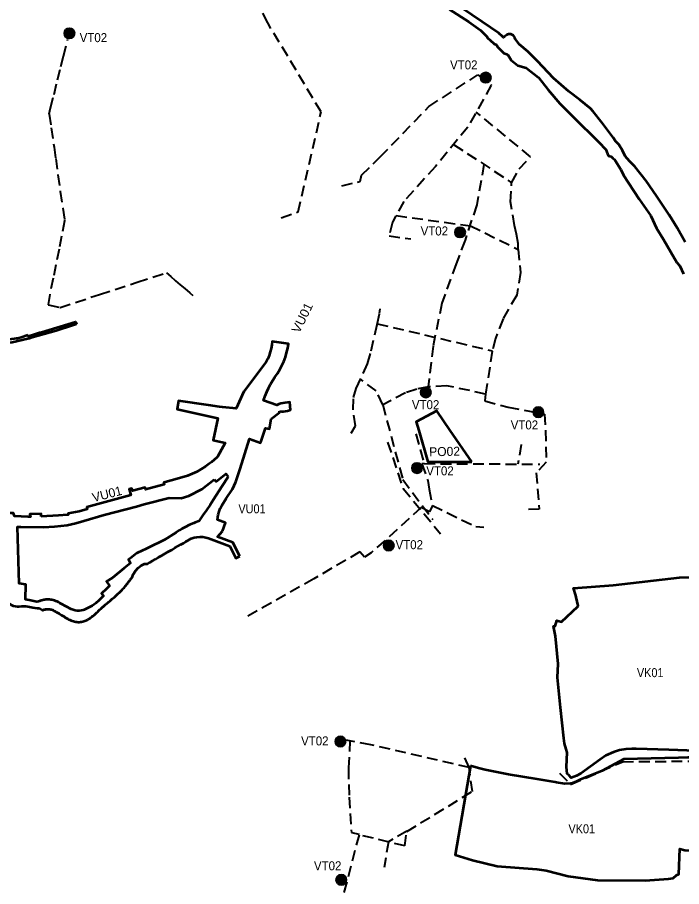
# Model space of a CAD drawing. Extents: x -650145 to -642675, y -1074338 to -1066803.
# Drawn here: x -646647 to -645175, y -1071056 to -1069131 of the extents above; entities that cross this region are included whole.
import ezdxf

# ---------------------------------------------------------------- set-up
doc = ezdxf.new("R2010")
doc.units = 0
doc.header["$LTSCALE"] = 8
doc.linetypes.add('MEDIUM_DASHED', pattern=[4.5, 3, -1.5])
for name, color, linetype, lineweight in [('12', 7, 'MEDIUM_DASHED', 40), ('13', 7, 'MEDIUM_DASHED', 40), ('15', 7, 'Continuous', 13), ('44', 7, 'Continuous', 53), ('45', 7, 'Continuous', 53), ('46', 7, 'Continuous', 53), ('53', 7, 'Continuous', 53)]:
    doc.layers.add(name, color=color, linetype=linetype, lineweight=lineweight)
for name, color, linetype in [('17', 7, 'Continuous'), ('2', 7, 'Continuous'), ('5', 7, 'Continuous'), ('8', 7, 'Continuous')]:
    doc.layers.add(name, color=color, linetype=linetype)

msp = doc.modelspace()

# ---------------------------------------------------------------- hatches: boundary and pattern name
at = {"layer": '15'}
for points in [[(-646519.621, -1069166.048, 1), (-646543.146, -1069166.048, 1)], [(-645597.068, -1069264.181, 1), (-645620.593, -1069264.181, 1)], [(-645654.023, -1069606.85, 1), (-645677.548, -1069606.85, 1)], [(-645729.982, -1069961.372, 1), (-645753.507, -1069961.372, 1)], [(-645480.488, -1070005.174, 1), (-645504.013, -1070005.174, 1)], [(-645749.33, -1070128.96, 1), (-645772.855, -1070128.96, 1)], [(-645812.096, -1070300.527, 1), (-645835.621, -1070300.527, 1)], [(-645919.09, -1070734.667, 1), (-645942.615, -1070734.667, 1)], [(-645917.104, -1071041.111, 1), (-645940.629, -1071041.111, 1)]]:
    msp.add_hatch(color=256, dxfattribs=at).paths.add_polyline_path(points)

# ---------------------------------------------------------------- linework, layer by layer
at = {"layer": '12'}
for p, q in [((-645679.959, -1069412.046), (-645551.493, -1069496.874)), ((-645849.328, -1069809.196), (-645594.304, -1069869.281)), ((-645530.465, -1070076.92), (-645537.502, -1070120.198)), ((-645787.95, -1070966.128), (-645887.342, -1070941.864))]:
    msp.add_line(p, q, dxfattribs=at)
for points in [[(-646062.183, -1069574.695), (-646024.736, -1069561.612), (-645973.562, -1069340.254), (-646092.013, -1069143.037), (-646157.557, -1069015.41), (-646220.085, -1068916.892), (-646248.016, -1068862.258), (-646295.932, -1068894.5), (-646451.322, -1069032.874)], [(-646576.25, -1069344.69), (-646576.07, -1069344.19), (-646572.92, -1069331.38), (-646565.43, -1069301.45), (-646557.53, -1069269.39), (-646550.09, -1069239.83), (-646544.34, -1069216.84), (-646534.934, -1069179.318)], [(-645927.806, -1069503.664), (-645886.806, -1069494.297), (-645883.788, -1069480.205), (-645842.55, -1069439.942), (-645734.927, -1069328.215), (-645626.154, -1069257.704), (-645596.435, -1069280.712), (-645648.533, -1069373.739), (-645720.378, -1069461.316), (-645790.62, -1069538.59), (-645815.779, -1069584.682), (-645822.696, -1069614.711), (-645775.097, -1069621.255)], [(-646576.25, -1069344.69), (-646576.14, -1069345.28), (-646571.6, -1069375.24), (-646565.13, -1069418.25), (-646561.67, -1069443.36), (-646557.02, -1069479.48), (-646551.76, -1069516.65), (-646546.19, -1069553.66), (-646542.189, -1069579.489), (-646541.86, -1069581.61), (-646548.99, -1069615.32), (-646554.11, -1069644.37), (-646561.65, -1069679.08), (-646567.03, -1069708.57), (-646575.01, -1069744.61), (-646578.22, -1069766.52), (-646578.238, -1069766.625), (-646578.433, -1069767.754), (-646552.777, -1069773.113), (-646552.12, -1069773.25), (-646464.51, -1069744.51), (-646380.87, -1069717.23), (-646346.59, -1069706.12), (-646316.394, -1069696.504), (-646316.32, -1069696.48), (-646306.32, -1069704.97), (-646296.979, -1069713.37), (-646296.125, -1069714.146), (-646285.929, -1069723.39), (-646275.84, -1069731.47), (-646264.46, -1069741.23), (-646257.888, -1069746.914)], [(-645807.67, -1069569.827), (-645642.853, -1069592.369), (-645537.006, -1069644.608), (-645537.068, -1069631.54), (-645540.509, -1069610.611), (-645545.036, -1069592.007), (-645553.718, -1069539.481), (-645551.493, -1069496.874), (-645535.107, -1069466.529), (-645509.579, -1069439.682), (-645629.872, -1069340.417)], [(-645612.686, -1069456.467), (-645628.75, -1069545.873), (-645654.668, -1069623.875), (-645674.387, -1069676.46), (-645706.032, -1069763.934), (-645725.616, -1069858.975), (-645736.083, -1069949.319)], [(-645537.006, -1069644.608), (-645531.552, -1069695.67), (-645540.071, -1069746.311), (-645570.504, -1069798.227), (-645587.257, -1069841.96), (-645594.542, -1069870.205), (-645609.199, -1069964.997), (-645695.3, -1069946.789), (-645735.674, -1069949.294), (-645761.611, -1069954.176), (-645786.679, -1069962.538), (-645837.185, -1069988.794), (-645851.6, -1069958.035), (-645886.355, -1069931.852)], [(-645906.816, -1070051.7), (-645897.34, -1070035.615), (-645902.834, -1069999.35), (-645901.735, -1069972.609), (-645895.874, -1069952.462), (-645870.943, -1069898.484), (-645862.678, -1069869.213), (-645849.656, -1069810.695), (-645844.459, -1069786.925), (-645843.101, -1069776.602)], [(-645609.199, -1069964.997), (-645611.007, -1069980.138), (-645559.306, -1069994.087), (-645478.278, -1070009.272), (-645476.409, -1070045.777), (-645475.095, -1070115.938), (-645496.905, -1070139.324), (-645490.337, -1070219.995), (-645518.762, -1070220.564)], [(-645837.185, -1069988.794), (-645792.73, -1070154.35), (-645726.373, -1070242.826)], [(-645763.769, -1070053.49), (-645745.016, -1070119.16), (-645488.654, -1070120.442)], [(-645826.322, -1070071.476), (-645791.882, -1070174.421), (-645708.828, -1070274.697)], [(-645745.016, -1070119.16), (-645750.773, -1070119.546), (-645737.216, -1070156.772), (-645734.164, -1070175.48), (-645727.06, -1070211.99), (-645630.95, -1070258.73), (-645613.049, -1070260.16)], [(-645727.06, -1070211.99), (-645733.17, -1070225.623), (-645751.944, -1070216.719), (-645862.549, -1070316.813), (-645877.139, -1070326.682), (-645887.867, -1070314.667), (-645989.89, -1070374.31), (-646136.792, -1070457.926)], [(-645645.314, -1070792.546), (-645863.469, -1070742.026), (-645925.077, -1070730.137)], [(-645909.628, -1070733.118), (-645913.153, -1070793.741), (-645911.597, -1070858.189), (-645906.549, -1070936.386), (-645889.059, -1070939.608)], [(-645638.383, -1070845.262), (-645645.314, -1070792.546), (-645658.84, -1070762.42)], [(-645787.95, -1070966.128), (-645783.846, -1070933.893), (-645638.383, -1070845.262)], [(-645783.721, -1070932.909), (-645824.424, -1070957.108), (-645833.925, -1071014.113)], [(-645889.511, -1070941.335), (-645965.547, -1071232.088), (-646030.617, -1071380.071), (-646083.181, -1071471.838), (-646148.926, -1071551.731), (-646210.712, -1071621.148), (-646257.454, -1071581.884), (-646334.001, -1071528.434)]]:
    msp.add_lwpolyline(points, dxfattribs=at)
at = {"layer": '13'}
msp.add_lwpolyline([(-645445.374, -1070804.496), (-645420.722, -1070830.204), (-645305.382, -1070779.425), (-645079.923, -1070777.683), (-644892.766, -1070773.328), (-644498.43, -1070726.295), (-644498.43, -1070726.295), (-644443.224, -1070697.577)], dxfattribs=at)
at = {"layer": '15', "lineweight": 35}
for centre in [(-646531.383, -1069166.048), (-645608.83, -1069264.181), (-645665.785, -1069606.85), (-645741.744, -1069961.372), (-645492.25, -1070005.174), (-645761.092, -1070128.96), (-645823.858, -1070300.527), (-645930.852, -1070734.667), (-645928.866, -1071041.111)]:
    msp.add_circle(centre, 11.762, dxfattribs=at)
at = {"layer": '44'}
for points in [[(-646515.63, -1069810.24), (-646522.32, -1069812.28), (-646560.92, -1069825.33), (-646613.65, -1069840.02), (-646620.06, -1069841.69), (-646629.83, -1069844.23), (-646635.93, -1069845.82), (-646658.5, -1069850.59), (-646689.73, -1069854.58), (-646705.87, -1069856.62), (-646717.66, -1069857.11), (-646729.54, -1069853.69)], [(-646593.34, -1069827.68), (-646518.19, -1069805.27), (-646515.63, -1069810.24)], [(-646729.24, -1069851.41), (-646723.5, -1069852.83), (-646719.82, -1069853.78), (-646689.63, -1069849.7), (-646689.8, -1069848.71), (-646664.22, -1069843.72), (-646648.18, -1069841.04), (-646648.28, -1069841.78), (-646638.34, -1069838.73), (-646623.31, -1069834.1)], [(-646623.31, -1069834.1), (-646622.54, -1069835.88), (-646622.19, -1069836.71), (-646597.29, -1069828.86), (-646593.34, -1069827.68)]]:
    msp.add_lwpolyline(points, dxfattribs=at)
at = {"layer": '45'}
for points in [[(-645688.87, -1069113.44), (-645646.08, -1069140.37), (-645620.2, -1069159.26), (-645606.11, -1069172.98), (-645603.91, -1069176.86), (-645599, -1069181.48), (-645590.41, -1069189.45), (-645584.73, -1069191.88), (-645582.63, -1069195.88), (-645568.9, -1069209.87), (-645562.17, -1069212.02), (-645560.72, -1069214.25), (-645559.33, -1069214.54), (-645552.2, -1069225.59), (-645537.44, -1069237.41), (-645519.59, -1069242.38), (-645491.63, -1069264.25), (-645470.44, -1069291.24), (-645444.62, -1069321.35), (-645405.7, -1069360.27), (-645368.13, -1069397.37), (-645358.04, -1069406.84), (-645342.49, -1069423.06), (-645339.31, -1069433.27), (-645336.66, -1069437.47), (-645330.57, -1069438.89), (-645327.2, -1069442.53), (-645323.36, -1069445.79), (-645322.13, -1069447.96), (-645309.62, -1069467.79), (-645303.57, -1069480.49), (-645268.57, -1069533.23), (-645242.75, -1069570.26), (-645230.42, -1069597.39), (-645230.42, -1069597.39)], [(-645253.4, -1069493.06), (-645278.31, -1069461.33), (-645290.5, -1069449.03), (-645299.61, -1069437.97), (-645306.16, -1069425.55), (-645314.14, -1069412.54), (-645321.1, -1069405.21), (-645326.59, -1069396.64), (-645350.63, -1069363.98), (-645371.12, -1069339.47), (-645376.38, -1069332.65), (-645400.07, -1069313.32), (-645424.8, -1069295.24), (-645458.45, -1069265.56), (-645494.13, -1069227.63), (-645515.89, -1069206.66), (-645534.25, -1069190.56), (-645543.43, -1069178.39), (-645544.154, -1069175.682), (-645544.448, -1069174.993), (-645545.631, -1069172.966), (-645547.269, -1069171.107), (-645548.594, -1069170.034), (-645550.076, -1069169.141), (-645551.674, -1069168.459), (-645553.344, -1069168.007), (-645555.036, -1069167.793), (-645556.702, -1069167.808), (-645558.298, -1069168.035), (-645559.793, -1069168.445), (-645561.162, -1069169.007), (-645561.794, -1069169.334), (-645562.95, -1069170.06), (-645567.5, -1069173.46), (-645569.81, -1069175.03), (-645571.9, -1069173.43), (-645579.94, -1069165.52), (-645616.63, -1069140.8), (-645662.44, -1069109.89)], [(-645166.67, -1069629), (-645184.88, -1069596.58), (-645202.56, -1069568.23), (-645230.1, -1069525.98), (-645253.4, -1069493.06)], [(-645230.42, -1069597.39), (-645214.76, -1069622.37), (-645198.41, -1069650.49), (-645185.17, -1069673.38), (-645179.12, -1069681.3), (-645170.3, -1069698.91)]]:
    msp.add_lwpolyline(points, dxfattribs=at)
at = {"layer": '46'}
msp.add_lwpolyline([(-645639.638, -1070114.895), (-645687.31, -1070045.724), (-645717.36, -1070002.12), (-645762.868, -1070026.606), (-645757.215, -1070045.97), (-645737.075, -1070114.955)], close=True, dxfattribs=at)
at = {"layer": '53'}
msp.add_line((-646436.406, -1070418.912), (-646431.413, -1070414.711), dxfattribs=at)
for points in [[(-646066.18, -1070003.075), (-646061.657, -1070003.566), (-646057.108, -1070003.593), (-646052.58, -1070003.156), (-646048.12, -1070002.26), (-646041.502, -1070000.228), (-646042.718, -1069982.76), (-646053.851, -1069984.206), (-646058.468, -1069984.901), (-646062.994, -1069986.051), (-646067.384, -1069987.645), (-646071.593, -1069989.666), (-646101.001, -1069979.408), (-646097.251, -1069968.66), (-646093.973, -1069960.063), (-646090.206, -1069951.669), (-646085.964, -1069943.504), (-646081.261, -1069935.596), (-646076.112, -1069927.971), (-646070.334, -1069919.66), (-646065.099, -1069910.998), (-646060.426, -1069902.02), (-646056.334, -1069892.762), (-646052.842, -1069883.262), (-646049.962, -1069873.559), (-646047.706, -1069863.691), (-646046.084, -1069853.701), (-646081.883, -1069848.398), (-646082.789, -1069856.304), (-646084.254, -1069864.127), (-646086.269, -1069871.826), (-646088.824, -1069879.363), (-646091.907, -1069886.7), (-646095.501, -1069893.8), (-646144.829, -1069959.738), (-646161.961, -1069997.236), (-646191.788, -1069994.17), (-646199.035, -1069993.103), (-646222.86, -1069989.593)], [(-646222.86, -1069989.593), (-646289.854, -1069979.726), (-646292.665, -1069998.812), (-646202.542, -1070018.378), (-646213.15, -1070067.24), (-646186.308, -1070073.067), (-646190.852, -1070081.164), (-646202.148, -1070102.585), (-646203.22, -1070104.042), (-646204.46, -1070105.36), (-646216.71, -1070116.09), (-646218.58, -1070117.728), (-646220.665, -1070119.081), (-646229.714, -1070125.737), (-646239.166, -1070131.809), (-646248.983, -1070137.27), (-646259.126, -1070142.1), (-646269.553, -1070146.279), (-646292.43, -1070152.746), (-646319.14, -1070160.204), (-646322.439, -1070161.099), (-646321.366, -1070165.285), (-646362.63, -1070176.349), (-646363.76, -1070172.308), (-646391.36, -1070179.795), (-646392.973, -1070174.016), (-646398.764, -1070175.587), (-646395.004, -1070189.06), (-646493.094, -1070215.306), (-646491.69, -1070220.183), (-646509.367, -1070225.035), (-646534.455, -1070229.96), (-646534.234, -1070232.344), (-646535.746, -1070232.706)], [(-646106.597, -1070069.459), (-646096.819, -1070040.415), (-646087.718, -1070041.752), (-646084.5, -1070020.01), (-646065.721, -1070006.267), (-646066.18, -1070003.075)], [(-646162.293, -1070159.269), (-646153.279, -1070131.047), (-646132.14, -1070064.521), (-646107.901, -1070072.976), (-646106.597, -1070069.459)], [(-646210.809, -1070154.566), (-646206.316, -1070158.936), (-646184.78, -1070141.8), (-646179.58, -1070148.76)], [(-646382.682, -1070213.977), (-646365.458, -1070209.154), (-646310.639, -1070194.623), (-646283.756, -1070195.86), (-646266.79, -1070190.647), (-646237.783, -1070175.765), (-646210.809, -1070154.566)], [(-646179.58, -1070148.76), (-646193.764, -1070170.033), (-646212.182, -1070198.396), (-646219.706, -1070210.367), (-646227.598, -1070222.099), (-646235.85, -1070233.58)], [(-646191.989, -1070268.868), (-646185.325, -1070250.01), (-646202.889, -1070243.725), (-646202.556, -1070238.126), (-646201.763, -1070232.574), (-646199.653, -1070225.42), (-646196.96, -1070218.464), (-646193.704, -1070211.754), (-646184.225, -1070196.405), (-646170.243, -1070175.74), (-646162.293, -1070159.269)], [(-646638.72, -1070258.98), (-646589.083, -1070260.095), (-646564.01, -1070258.35), (-646536.32, -1070255.575), (-646517.124, -1070251.263), (-646499.702, -1070246), (-646454.39, -1070232.782), (-646382.682, -1070213.977)], [(-646593.751, -1070236.292), (-646594.226, -1070230.306), (-646619.339, -1070231.28), (-646617.731, -1070236.951), (-646623.104, -1070237.199), (-646653.044, -1070235.3), (-646655.238, -1070229.03), (-646661.949, -1070228.719), (-646668.506, -1070228.289), (-646668.854, -1070233.592), (-646679.445, -1070232.801), (-646679.103, -1070227.593), (-646701.794, -1070226.105), (-646702.125, -1070232.096), (-646702.089, -1070232.106), (-646717.674, -1070230.771)], [(-646535.746, -1070232.706), (-646555.792, -1070233.748), (-646593.751, -1070236.292)], [(-646235.85, -1070233.58), (-646244.35, -1070246.34), (-646252.705, -1070249.775), (-646255.67, -1070250.98), (-646265.5, -1070255.029), (-646274.745, -1070259.625), (-646282.19, -1070263.48), (-646287.404, -1070266.885), (-646294.817, -1070271.893), (-646320.94, -1070288.18), (-646332.204, -1070293.817), (-646344.852, -1070299.906), (-646355.683, -1070304.877), (-646356.951, -1070305.96), (-646362.765, -1070308.54), (-646369.65, -1070311.87), (-646382.167, -1070317.859), (-646395.86, -1070328.368), (-646400.36, -1070331.84), (-646397.465, -1070337.23), (-646396.14, -1070339.32), (-646410.317, -1070350.805), (-646435.519, -1070371.968), (-646448.878, -1070380.488), (-646442.41, -1070389.923), (-646444.441, -1070391.921), (-646449.294, -1070396.547), (-646460.148, -1070406.493), (-646455.582, -1070411.766), (-646466.137, -1070422.543)], [(-646642.572, -1070384.627), (-646646.36, -1070259.52), (-646638.72, -1070258.98)], [(-646153.487, -1070323.853), (-646168.852, -1070293.991), (-646203.108, -1070281.395), (-646191.989, -1070268.868)], [(-646400.089, -1070381.198), (-646398.865, -1070379.572), (-646397.635, -1070377.949), (-646396.388, -1070376.32), (-646395.111, -1070374.679), (-646393.795, -1070373.021), (-646392.431, -1070371.34), (-646389.73, -1070364.95), (-646385.129, -1070356.758), (-646378.984, -1070350.017), (-646372.48, -1070344.965), (-646365.19, -1070341.06), (-646358.18, -1070341.294), (-646352.974, -1070337.977), (-646347.116, -1070334.392), (-646340.694, -1070330.575), (-646333.841, -1070326.588), (-646326.691, -1070322.488), (-646319.372, -1070318.331), (-646312.011, -1070314.171), (-646304.73, -1070310.059), (-646297.651, -1070306.046), (-646290.895, -1070302.182), (-646284.583, -1070298.516), (-646278.846, -1070295.116), (-646273.693, -1070292.027), (-646269.084, -1070289.272), (-646264.973, -1070286.873), (-646261.318, -1070284.844)], [(-646261.318, -1070284.844), (-646255.08, -1070283.066), (-646248.694, -1070281.932), (-646242.226, -1070281.453), (-646235.742, -1070281.633), (-646229.311, -1070282.472), (-646222.998, -1070283.959), (-646175.84, -1070302.265), (-646162.379, -1070328.428), (-646153.487, -1070323.853)], [(-645442.834, -1070659.455), (-645449.82, -1070592.72), (-645448.36, -1070563), (-645454.02, -1070501.52), (-645458.46, -1070478.86), (-645455.09, -1070479.21), (-645451.226, -1070466.394), (-645440.61, -1070469.53), (-645404.4, -1070435.88), (-645404.34, -1070433.93), (-645408.66, -1070414.62), (-645409.38, -1070411.41), (-645414.65, -1070395.37), (-645326.62, -1070388.32), (-645179.26, -1070371.74), (-645006.86, -1070365.38), (-645003.102, -1070365.432), (-645003.03, -1070365.427), (-645001.312, -1070412.099), (-645004.327, -1070461.264), (-645014.277, -1070543.11), (-645023.048, -1070595.033), (-645023.346, -1070596.478)], [(-646596.162, -1070423.238), (-646597.944, -1070423.75), (-646599.624, -1070424.214), (-646603.325, -1070425.151), (-646620.675, -1070421.365), (-646624.719, -1070420.631), (-646628.806, -1070420.182), (-646627.927, -1070386.72), (-646642.572, -1070384.627), (-646642.573, -1070384.627), (-646642.572, -1070384.627)], [(-646431.413, -1070414.711), (-646427.802, -1070411.521), (-646416.451, -1070400.677), (-646414.262, -1070398.359), (-646412.205, -1070396.117), (-646410.306, -1070393.979), (-646408.549, -1070391.937), (-646406.919, -1070389.982), (-646405.398, -1070388.104), (-646403.972, -1070386.295), (-646402.625, -1070384.549), (-646401.337, -1070382.855), (-646400.093, -1070381.203), (-646400.089, -1070381.198)], [(-646664.091, -1070429.494), (-646660.264, -1070432.064), (-646656.068, -1070433.973), (-646651.616, -1070435.17), (-646647.029, -1070435.621), (-646642.429, -1070435.315), (-646637.107, -1070434.832), (-646632.649, -1070434.654), (-646628.195, -1070434.931), (-646623.793, -1070435.659), (-646612.723, -1070438.074), (-646607.615, -1070438.944), (-646602.448, -1070439.34), (-646597.266, -1070439.257)], [(-646597.266, -1070439.257), (-646590.957, -1070443.592), (-646590.363, -1070443.421), (-646588.587, -1070442.911), (-646586.916, -1070442.451), (-646585.345, -1070442.053), (-646583.87, -1070441.727), (-646582.482, -1070441.48), (-646581.151, -1070441.309), (-646579.837, -1070441.214), (-646578.514, -1070441.195), (-646577.157, -1070441.258), (-646575.74, -1070441.412), (-646574.239, -1070441.67), (-646572.632, -1070442.047), (-646570.899, -1070442.563), (-646569.025, -1070443.236), (-646566.991, -1070444.089), (-646564.759, -1070445.152), (-646562.331, -1070446.421), (-646559.752, -1070447.864), (-646557.065, -1070449.444), (-646554.308, -1070451.123), (-646551.512, -1070452.866), (-646548.704, -1070454.638), (-646545.907, -1070456.406), (-646543.14, -1070458.14), (-646540.419, -1070459.807), (-646537.765, -1070461.374), (-646535.178, -1070462.83), (-646532.64, -1070464.172), (-646530.129, -1070465.399), (-646527.625, -1070466.508), (-646525.108, -1070467.491), (-646522.562, -1070468.338), (-646519.978, -1070469.035), (-646517.352, -1070469.565), (-646514.695, -1070469.913), (-646512.039, -1070470.069), (-646509.422, -1070470.039), (-646506.861, -1070469.835), (-646504.363, -1070469.473), (-646501.935, -1070468.967), (-646499.583, -1070468.332), (-646497.308, -1070467.581), (-646495.112, -1070466.727), (-646492.994, -1070465.784), (-646490.954, -1070464.761), (-646488.99, -1070463.667), (-646487.096, -1070462.511), (-646485.267, -1070461.299), (-646483.498, -1070460.038), (-646481.78, -1070458.736), (-646480.104, -1070457.395), (-646478.459, -1070456.019), (-646476.835, -1070454.611), (-646475.22, -1070453.171), (-646473.603, -1070451.697), (-646471.973, -1070450.189), (-646470.327, -1070448.652), (-646468.67, -1070447.095), (-646467.007, -1070445.529), (-646465.346, -1070443.966), (-646463.692, -1070442.418), (-646462.055, -1070440.896), (-646460.441, -1070439.413), (-646458.861, -1070437.984), (-646457.32, -1070436.617), (-646455.804, -1070435.304), (-646454.279, -1070434.009), (-646452.72, -1070432.705), (-646451.108, -1070431.367), (-646449.427, -1070429.974), (-646447.661, -1070428.506), (-646445.799, -1070426.943), (-646443.829, -1070425.265), (-646441.789, -1070423.499), (-646439.621, -1070421.668), (-646437.3, -1070419.674), (-646436.406, -1070418.912)], [(-646549.763, -1070429.389), (-646552.336, -1070427.949), (-646555.377, -1070426.36), (-646558.411, -1070424.915), (-646561.41, -1070423.657), (-646564.352, -1070422.601), (-646567.234, -1070421.744), (-646570.059, -1070421.08), (-646572.827, -1070420.605), (-646575.534, -1070420.311), (-646578.175, -1070420.188), (-646580.746, -1070420.225), (-646583.243, -1070420.406), (-646585.658, -1070420.715), (-646587.978, -1070421.128), (-646590.186, -1070421.616), (-646592.284, -1070422.147), (-646594.275, -1070422.696), (-646596.16, -1070423.237), (-646596.162, -1070423.238)], [(-646500.604, -1070443.707), (-646504.98, -1070444.845), (-646509.534, -1070445.391), (-646514.121, -1070445.32), (-646518.656, -1070444.632), (-646523.057, -1070443.341), (-646527.245, -1070441.469), (-646549.763, -1070429.389)], [(-646466.137, -1070422.543), (-646472.503, -1070428.341), (-646476.354, -1070431.539), (-646480.664, -1070434.085), (-646498.418, -1070442.745), (-646500.604, -1070443.707)], [(-645023.346, -1070596.478), (-645028.384, -1070620.876), (-645039.574, -1070675.065), (-645045.493, -1070696.321), (-645059.308, -1070747.712), (-645059.421, -1070749.039), (-645060.46, -1070749.1), (-645065.17, -1070751.39), (-645070.3, -1070755.92), (-645079.38, -1070756.91), (-645085.58, -1070758.04), (-645163.06, -1070754.64), (-645202.96, -1070752.89), (-645275.236, -1070750.954)], [(-645435.711, -1070727.497), (-645442.836, -1070659.455), (-645442.834, -1070659.455)], [(-645275.236, -1070750.954), (-645285.11, -1070750.69), (-645298.41, -1070751.48), (-645312.2, -1070753.77), (-645325.82, -1070757.94), (-645342.41, -1070765.76), (-645354.98, -1070774.28), (-645398.04, -1070805.44), (-645407.37, -1070810.95), (-645419.18, -1070815.44), (-645424.969, -1070809.563), (-645428.39, -1070806.09), (-645430, -1070790.68), (-645428.73, -1070758.67), (-645430.84, -1070751.43), (-645434.53, -1070738.77), (-645435.711, -1070727.497)], [(-645100.268, -1070771.946), (-645143, -1070770), (-645161, -1070770), (-645182, -1070771), (-645303, -1070774), (-645351, -1070800), (-645400.05, -1070819.84), (-645406.09, -1070822.34), (-645409.52, -1070823.76), (-645418.67, -1070827.72), (-645421.09, -1070827.89), (-645433.49, -1070828.76), (-645452.31, -1070825.52), (-645455.184, -1070825.042)], [(-645642.52, -1070788.7), (-645676.292, -1070985.89), (-645637.94, -1070997.4), (-645583.18, -1071010.7), (-645495.87, -1071017.81)], [(-645455.184, -1070825.042), (-645494.82, -1070818.45), (-645558.3, -1070808), (-645610.25, -1070797.55), (-645625, -1070793.5), (-645642.52, -1070788.7)], [(-645495.87, -1071017.81), (-645475.01, -1071020.72), (-645426.38, -1071032.8), (-645361.54, -1071041.54), (-645255.93, -1071042.36), (-645203.66, -1071038.81), (-645193.24, -1071037.31), (-645186.18, -1071030.83), (-645180.72, -1071028.86), (-645178.73, -1070972.35), (-645167.47, -1070975.2), (-645134.973, -1070977.077), (-645134.973, -1070977.077), (-645130.749, -1070959.561)]]:
    msp.add_lwpolyline(points, dxfattribs=at)

# ---------------------------------------------------------------- texts
at = {"layer": '17', "width": 0.95}
for p in [(-646508.55, -1069185.576), (-645687.853, -1069245.943), (-645753.107, -1069613.825), (-645772.41, -1069998.573), (-645553.491, -1070043.441), (-645740.516, -1070145.097), (-645808.603, -1070308.709), (-646017.95, -1070743.342), (-645989.445, -1071019.949)]:
    msp.add_text('VT02', height=20, dxfattribs=at).set_placement(p)
at = {"layer": '2', "width": 1.05}
msp.add_text('VU01', height=20, rotation=63.768, dxfattribs=at).set_placement((-646021.976, -1069831.992))
at = {"layer": '2'}
msp.add_text('VU01', height=20, rotation=14.511, dxfattribs=at).set_placement((-646477.81, -1070204.543))
at = {"layer": '2', "width": 0.9}
msp.add_text('VU01', height=20, dxfattribs=at).set_placement((-646156.89, -1070229.206))
at = {"layer": '5'}
msp.add_text('PO02', height=20, rotation=1.088, dxfattribs=at).set_placement((-645734, -1070102.958))
at = {"layer": '8', "width": 0.9}
for p in [(-645273.856, -1070592.16), (-645425.521, -1070938.011)]:
    msp.add_text('VK01', height=20, dxfattribs=at).set_placement(p)

doc.saveas('drawing.dxf')
